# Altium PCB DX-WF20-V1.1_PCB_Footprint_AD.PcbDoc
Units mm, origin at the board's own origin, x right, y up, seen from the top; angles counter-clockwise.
Board outline 152.4 x 101.6 mm, 2 copper layers (Top, Bottom), stack 0.323 mm thick; 1 components, 0 nets, 52 pads, 0 vias.
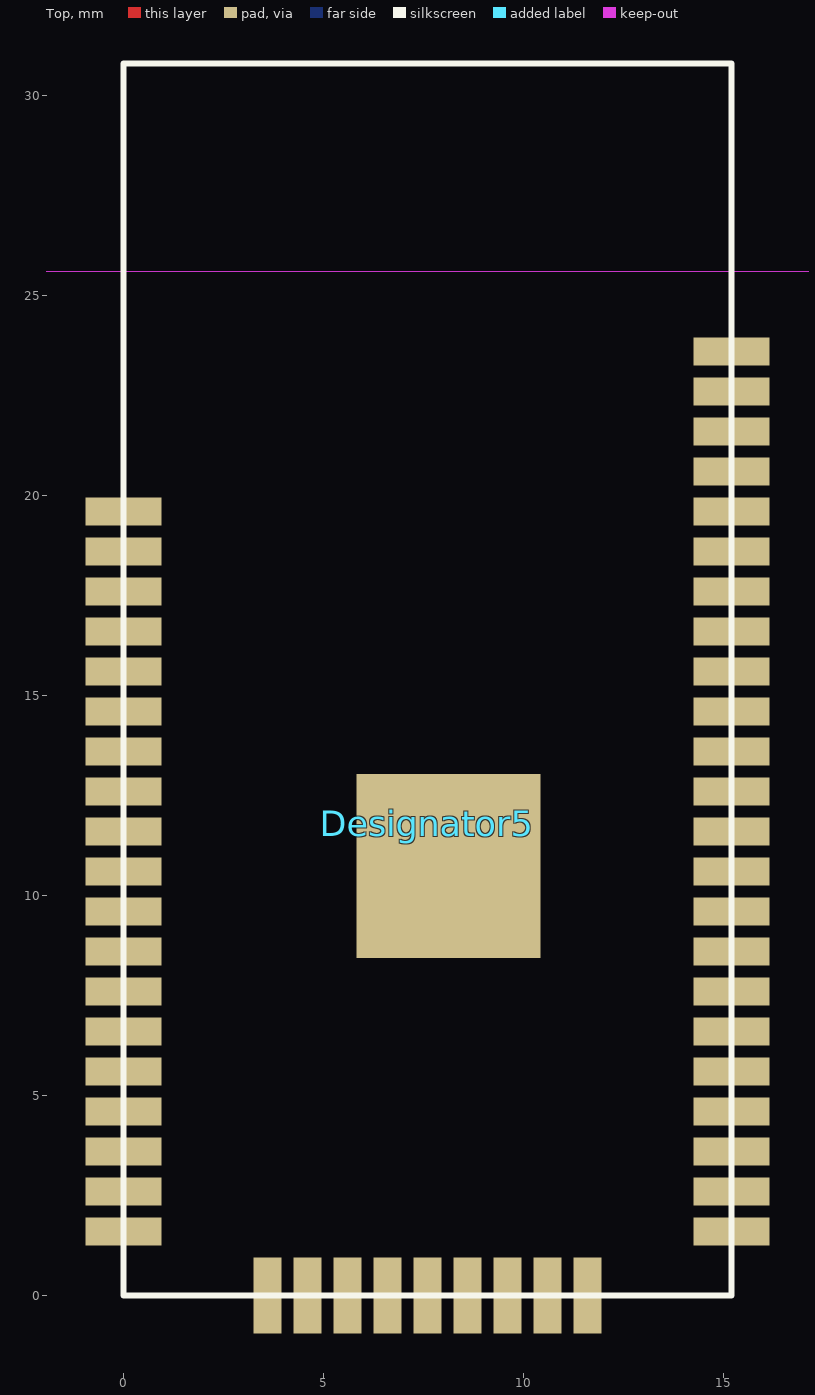
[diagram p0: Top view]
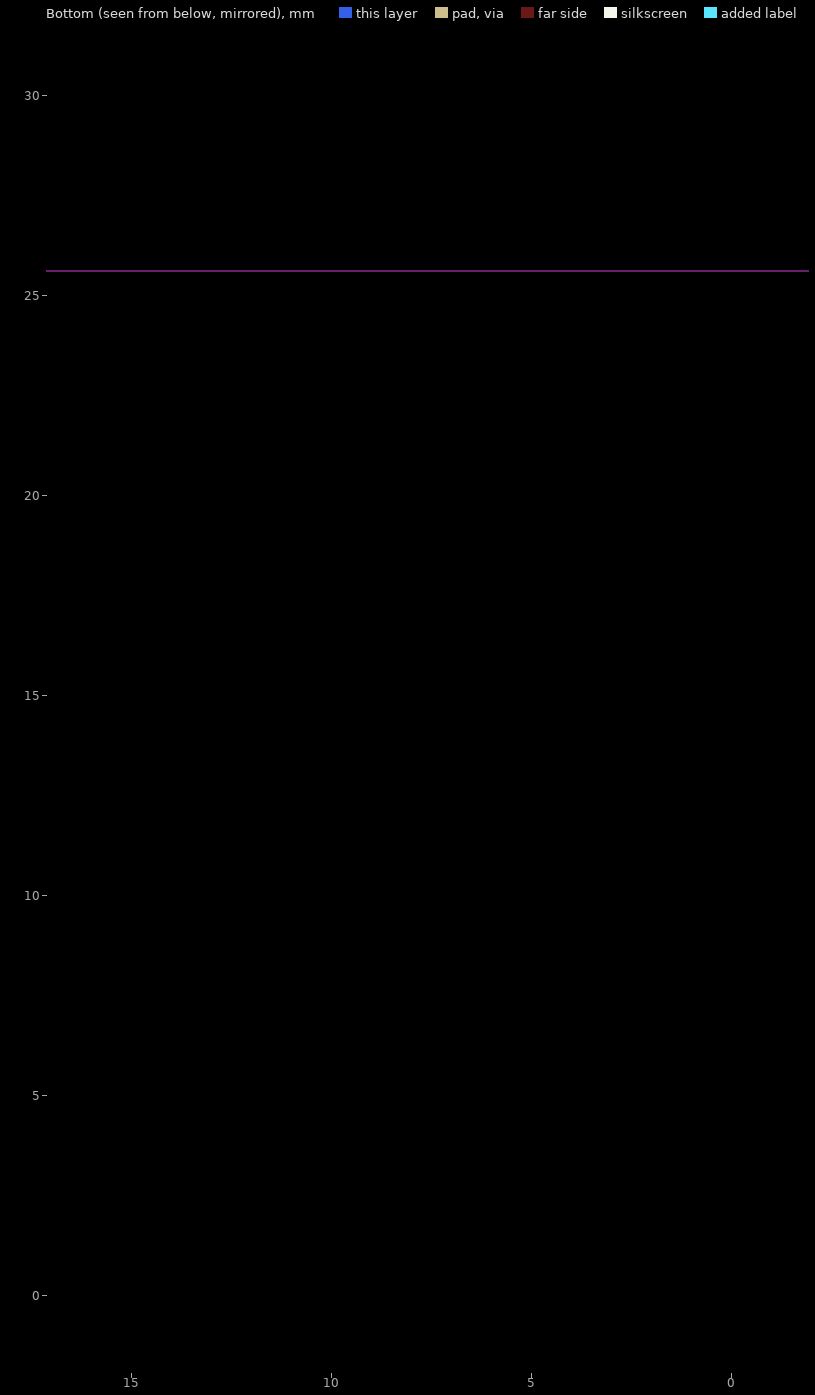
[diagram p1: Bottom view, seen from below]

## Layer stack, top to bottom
Solder Mask Top: solder mask 0.0102, Solder Resist, Dk 3.5
Top: signal copper 0.0343
Dielectric 1: dielectric 0.254, FR-4, Dk 4.3
Bottom: signal copper 0.0343
Solder Mask Bottom: solder mask 0.0102, Solder Resist, Dk 3.5

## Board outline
-694.363,-676.631 -541.963,-676.631 -541.963,-575.031 -694.363,-575.031

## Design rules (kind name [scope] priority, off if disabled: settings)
Clearance "'Default' PADS rule_17" [All] p1: gap=0.152 ignorepadtopadclearanceinfootprint=FALSE except(0: Arc-Hole Track-Hole SMDPad-Hole THPad-Hole Via-Hole Fill-Hole Poly-Hole Region-Hole Text-Hole)
Clearance "'Default' PADS rule_16" [InPolygon vs InPolygon] p2: gap=0.2 ignorepadtopadclearanceinfootprint=FALSE except(0: Arc-Hole Track-Hole SMDPad-Hole THPad-Hole Via-Hole Fill-Hole Poly-Hole Region-Hole Text-Hole)
Clearance "'Default' PADS rule_15" [All] p3: gap=0.152 ignorepadtopadclearanceinfootprint=FALSE except(0: Arc-Hole Track-Hole SMDPad-Hole THPad-Hole Via-Hole Fill-Hole Poly-Hole Region-Hole Text-Hole)
ComponentClearance "'Default' PADS rule_12" [All] p1: gap=0 collisioncheckmode=3 verticalgap=0.254 showdistances=FALSE
FlightTimeFalling "'Default' PADS rule_10" [All] p1: maximum=10.00
FlightTimeRising "'Default' PADS rule_9" [All] p1: maximum=10.00
Length "'Default' PADS rule_5" [All] p1: maxlimit=1270 minlimit=0
MatchedLengths "'Default' PADS rule_11" [InNetClass('All Nets')] p1: tolerance=5.08 checknetsindiffpair=TRUE checkdiffpairvsdiffpair=FALSE checkxsignals=FALSE checkothers=FALSE
MaxMinImpedance "'Default' PADS rule_8" [All] p1: minimum=50.00 maximum=150.0
ParallelSegment "'Default' PADS rule_7" [All] p1: limit=25.4 gap=5.08
ParallelSegment "'Default' PADS rule_6" [All] p2: limit=25.4 gap=5.08
PlaneClearance "'Default' PADS rule_14" [All] p1: clearance=0.2
PlaneConnect "Power Plane Connect Style - Via from round thru-hole global defaults" [IsVia] p1: planeconnectstyle=Direct reliefexpansion=0.508 reliefentries=4 reliefconductorwidth=0.381 reliefairgap=0.254
PlaneConnect "Power Plane Connect Style - Round thru-hole pad from global defaults" [IsPad And OnMultiLayer And (PadShape_MidLayer1 = 'Round') And (PadXSize_MidLayer1 = PadYSize_MidLayer1)] p2: planeconnectstyle=Direct reliefexpansion=0.508 reliefentries=4 reliefconductorwidth=0.381 reliefairgap=0.254
PlaneConnect "Power Plane Connect Style - Square thru-hole pad from global defaults" [IsPad And OnMultiLayer And ((PadShape_MidLayer1 = 'Rectangular') Or (PadShape_MidLayer1 = 'Octagonal') Or (PadShape_MidLayer1 = 'Rounded Rectangle')) And (PadXSize_MidLayer1 = PadYSize_MidLayer1)] p3: planeconnectstyle=Direct reliefexpansion=0.508 reliefentries=4 reliefconductorwidth=0.381 reliefairgap=0.254
PlaneConnect "Power Plane Connect Style - Rect thru-hole pad from global defaults" [IsPad And OnMultiLayer And ((PadShape_MidLayer1 = 'Rectangular') Or (PadShape_MidLayer1 = 'Octagonal') Or (PadShape_MidLayer1 = 'Rounded Rectangle')) And (PadXSize_MidLayer1 <> PadYSize_MidLayer1)] p4: planeconnectstyle=Direct reliefexpansion=0.508 reliefentries=4 reliefconductorwidth=0.381 reliefairgap=0.254
PlaneConnect "Power Plane Connect Style - Square-rect thru-hole pad from global defaults" [IsPad And OnMultiLayer And (PadShape_MidLayer1 = 'Rounded Rectangle') And (PadXSize_MidLayer1 = PadYSize_MidLayer1) And (Pad_CornerRadius_MidLayer1 = '0%')] p5: planeconnectstyle=Direct reliefexpansion=0.508 reliefentries=4 reliefconductorwidth=0.381 reliefairgap=0.254
PlaneConnect "Power Plane Connect Style - Oval thru-hole pad from global defaults" [IsPad And OnMultiLayer And (PadShape_MidLayer1 = 'Round') And (PadXSize_MidLayer1 <> PadYSize_MidLayer1)] p6: planeconnectstyle=Direct reliefexpansion=0.508 reliefentries=4 reliefconductorwidth=0.381 reliefairgap=0.254
PlaneConnect "Power Plane Connect Style - Round-oval thru-hole pad from global defaults" [IsPad And OnMultiLayer And (PadShape_MidLayer1 = 'Rounded Rectangle') And (PadXSize_MidLayer1 = PadYSize_MidLayer1) And (Pad_CornerRadius_MidLayer1 = '100%')] p7: planeconnectstyle=Direct reliefexpansion=0.508 reliefentries=4 reliefconductorwidth=0.381 reliefairgap=0.254
PolygonConnect "Polygon Connect Style - Bottom Round SMD from global defaults" [IsSMTPin And (PadShape_BottomLayer = 'Round') And (PadXSize_BottomLayer = PADYSize_BottomLayer) vs Layer = 'Bottom'] p1: connectstyle=Direct reliefconductorwidth=0.254 reliefentries=4 polygonreliefangle="45 Angle" airgapwidth=0.254
PolygonConnect "Polygon Connect Style - Top Round SMD from global defaults" [IsSMTPin And (PadShape_TopLayer = 'Round') And (PadXSize_TopLayer = PADYSize_TopLayer) vs Layer = 'Top'] p2: connectstyle=Direct reliefconductorwidth=0.254 reliefentries=4 polygonreliefangle="45 Angle" airgapwidth=0.254
PolygonConnect "Polygon Connect Style - Bottom Square SMD from global defaults 1" [IsSMTPin And (PadShape_BottomLayer = 'Rectangular') And (PadXSize_BottomLayer = PADYSize_BottomLayer) vs Layer = 'Bottom'] p3: connectstyle=Direct reliefconductorwidth=0.254 reliefentries=4 polygonreliefangle="45 Angle" airgapwidth=0.254
PolygonConnect "Polygon Connect Style - Bottom Square SMD from global defaults 2" [IsSMTPin And (PadShape_BottomLayer = 'Octagonal') And (PadXSize_BottomLayer = PADYSize_BottomLayer) vs Layer = 'Bottom'] p4: connectstyle=Direct reliefconductorwidth=0.254 reliefentries=4 polygonreliefangle="45 Angle" airgapwidth=0.254
PolygonConnect "Polygon Connect Style - Bottom Square SMD from global defaults 3" [IsSMTPin And (PadShape_BottomLayer = 'Rounded Rectangle') And (PadXSize_BottomLayer = PADYSize_BottomLayer) vs Layer = 'Bottom'] p5: connectstyle=Direct reliefconductorwidth=0.254 reliefentries=4 polygonreliefangle="45 Angle" airgapwidth=0.254
PolygonConnect "Polygon Connect Style - Top Square SMD from global defaults 1" [IsSMTPin And (PadShape_TopLayer = 'Rectangular') And (PadXSize_TopLayer = PADYSize_TopLayer) vs Layer = 'Top'] p6: connectstyle=Direct reliefconductorwidth=0.254 reliefentries=4 polygonreliefangle="45 Angle" airgapwidth=0.254
PolygonConnect "Polygon Connect Style - Top Square SMD from global defaults 2" [IsSMTPin And (PadShape_TopLayer = 'Octagonal') And (PadXSize_TopLayer = PADYSize_TopLayer) vs Layer = 'Top'] p7: connectstyle=Direct reliefconductorwidth=0.254 reliefentries=4 polygonreliefangle="45 Angle" airgapwidth=0.254
PolygonConnect "Polygon Connect Style - Top Square SMD from global defaults 3" [IsSMTPin And (PadShape_TopLayer = 'Rounded Rectangle') And (PadXSize_TopLayer = PADYSize_TopLayer) vs Layer = 'Top'] p8: connectstyle=Direct reliefconductorwidth=0.254 reliefentries=4 polygonreliefangle="45 Angle" airgapwidth=0.254
PolygonConnect "Polygon Connect Style - Bottom Rect SMD from global defaults 1" [IsSMTPin And (PadShape_BottomLayer = 'Rectangular') And (PadXSize_BottomLayer <> PADYSize_BottomLayer) vs Layer = 'Bottom'] p9: connectstyle=Direct reliefconductorwidth=0.254 reliefentries=4 polygonreliefangle="45 Angle" airgapwidth=0.254
PolygonConnect "Polygon Connect Style - Bottom Rect SMD from global defaults 2" [IsSMTPin And (PadShape_BottomLayer = 'Octagonal') And (PadXSize_BottomLayer <> PADYSize_BottomLayer) vs Layer = 'Bottom'] p10: connectstyle=Direct reliefconductorwidth=0.254 reliefentries=4 polygonreliefangle="45 Angle" airgapwidth=0.254
PolygonConnect "Polygon Connect Style - Bottom Rect SMD from global defaults 3" [IsSMTPin And (PadShape_BottomLayer = 'Rounded Rectangle') And (PadXSize_BottomLayer <> PADYSize_BottomLayer) vs Layer = 'Bottom'] p11: connectstyle=Direct reliefconductorwidth=0.254 reliefentries=4 polygonreliefangle="45 Angle" airgapwidth=0.254
PolygonConnect "Polygon Connect Style - Bottom Square-rect SMD pad from global defaults" [IsSMTPin And (PadShape_BottomLayer = 'Rounded Rectangle') And (PadXSize_BottomLayer = PADYSize_BottomLayer) And (Pad_CornerRadius_BottomLayer = '0%') vs Layer = 'Bottom'] p12: connectstyle=Direct reliefconductorwidth=0.254 reliefentries=4 polygonreliefangle="45 Angle" airgapwidth=0.254
PolygonConnect "Polygon Connect Style - Top Rect SMD from global defaults 1" [IsSMTPin And (PadShape_TopLayer = 'Rectangular') And (PadXSize_TopLayer <> PADYSize_TopLayer) vs Layer = 'Top'] p13: connectstyle=Direct reliefconductorwidth=0.254 reliefentries=4 polygonreliefangle="45 Angle" airgapwidth=0.254
PolygonConnect "Polygon Connect Style - Top Rect SMD from global defaults 2" [IsSMTPin And (PadShape_TopLayer = 'Octagonal') And (PadXSize_TopLayer <> PADYSize_TopLayer) vs Layer = 'Top'] p14: connectstyle=Direct reliefconductorwidth=0.254 reliefentries=4 polygonreliefangle="45 Angle" airgapwidth=0.254
PolygonConnect "Polygon Connect Style - Top Rect SMD from global defaults 3" [IsSMTPin And (PadShape_TopLayer = 'Rounded Rectangle') And (PadXSize_TopLayer <> PADYSize_TopLayer) vs Layer = 'Top'] p15: connectstyle=Direct reliefconductorwidth=0.254 reliefentries=4 polygonreliefangle="45 Angle" airgapwidth=0.254
PolygonConnect "Polygon Connect Style - Top Square-rect SMD pad from global defaults" [IsSMTPin And (PadShape_TopLayer = 'Rounded Rectangle') And (PadXSize_TopLayer = PADYSize_TopLayer) And (Pad_CornerRadius_TopLayer = '0%') vs Layer = 'Top'] p16: connectstyle=Direct reliefconductorwidth=0.254 reliefentries=4 polygonreliefangle="45 Angle" airgapwidth=0.254
PolygonConnect "Polygon Connect Style - Bottom Oval SMD from global defaults" [IsSMTPin And (PadShape_BottomLayer = 'Round') And (PadXSize_BottomLayer <> PADYSize_BottomLayer) vs Layer = 'Bottom'] p17: connectstyle=Direct reliefconductorwidth=0.254 reliefentries=4 polygonreliefangle="45 Angle" airgapwidth=0.254
PolygonConnect "Polygon Connect Style - Bottom Round-oval SMD pad from global defaults" [IsSMTPin And (PadShape_BottomLayer = 'Rounded Rectangle') And (PadXSize_BottomLayer = PADYSize_BottomLayer) And (Pad_CornerRadius_BottomLayer = '100%') vs Layer = 'Bottom'] p18: connectstyle=Direct reliefconductorwidth=0.254 reliefentries=4 polygonreliefangle="45 Angle" airgapwidth=0.254
PolygonConnect "Polygon Connect Style - Top Oval SMD from global defaults" [IsSMTPin And (PadShape_TopLayer = 'Round') And (PadXSize_TopLayer <> PADYSize_TopLayer) vs Layer = 'Top'] p19: connectstyle=Direct reliefconductorwidth=0.254 reliefentries=4 polygonreliefangle="45 Angle" airgapwidth=0.254
PolygonConnect "Polygon Connect Style - Top Round-oval SMD pad from global defaults" [IsSMTPin And (PadShape_TopLayer = 'Rounded Rectangle') And (PadXSize_TopLayer = PADYSize_TopLayer) And (Pad_CornerRadius_TopLayer = '100%') vs Layer = 'Top'] p20: connectstyle=Direct reliefconductorwidth=0.254 reliefentries=4 polygonreliefangle="45 Angle" airgapwidth=0.254
PolygonConnect "Polygon Connect Style - Via from round thru-hole global defaults_18" [IsVia] p21: connectstyle=Direct reliefconductorwidth=0.381 reliefentries=4 polygonreliefangle="45 Angle" airgapwidth=0.254
PolygonConnect "Polygon Connect Style - Bottom Round thru-hole pad from global defaults" [IsPad And OnMultiLayer And (PadShape_BottomLayer = 'Round') And (PadXSize_BottomLayer = PADYSize_BottomLayer) vs Layer = 'Bottom'] p22: connectstyle=Direct reliefconductorwidth=0.381 reliefentries=4 polygonreliefangle="45 Angle" airgapwidth=0.254
PolygonConnect "Polygon Connect Style - Via from round thru-hole global defaults" [IsVia] p23: connectstyle=Direct reliefconductorwidth=0.381 reliefentries=4 polygonreliefangle="45 Angle" airgapwidth=0.254
PolygonConnect "Polygon Connect Style - Top Round thru-hole pad from global defaults" [IsPad And OnMultiLayer And (PadShape_TopLayer = 'Round') And (PadXSize_TopLayer = PADYSize_TopLayer) vs Layer = 'Top'] p24: connectstyle=Direct reliefconductorwidth=0.381 reliefentries=4 polygonreliefangle="45 Angle" airgapwidth=0.254
PolygonConnect "Polygon Connect Style - Bottom Square thru-hole pad from global defaults" [IsPad And OnMultiLayer And ((PadShape_BottomLayer = 'Rectangular') Or (PadShape_BottomLayer = 'Octagonal') Or (PadShape_BottomLayer = 'Rounded Rectangle')) And (PadXSize_BottomLayer = PADYSize_BottomLayer) vs Layer = 'Bottom'] p25: connectstyle=Direct reliefconductorwidth=0.381 reliefentries=4 polygonreliefangle="45 Angle" airgapwidth=0.254
PolygonConnect "Polygon Connect Style - Top Square thru-hole pad from global defaults" [IsPad And OnMultiLayer And ((PadShape_TopLayer = 'Rectangular') Or (PadShape_TopLayer = 'Octagonal') Or (PadShape_TopLayer = 'Rounded Rectangle')) And (PadXSize_TopLayer = PADYSize_TopLayer) vs Layer = 'Top'] p26: connectstyle=Direct reliefconductorwidth=0.381 reliefentries=4 polygonreliefangle="45 Angle" airgapwidth=0.254
PolygonConnect "Polygon Connect Style - Bottom Rect thru-hole pad from global defaults" [IsPad And OnMultiLayer And ((PadShape_BottomLayer = 'Rectangular') Or (PadShape_BottomLayer = 'Octagonal') Or (PadShape_BottomLayer = 'Rounded Rectangle')) And (PadXSize_BottomLayer <> PADYSize_BottomLayer) vs Layer = 'Bottom'] p27: connectstyle=Direct reliefconductorwidth=0.381 reliefentries=4 polygonreliefangle="45 Angle" airgapwidth=0.254
PolygonConnect "Polygon Connect Style - Bottom Square-rect thru-hole pad from global defaults" [IsPad And OnMultiLayer And (PadShape_BottomLayer = 'Rounded Rectangle') And (PadXSize_BottomLayer = PADYSize_BottomLayer) And (Pad_CornerRadius_BottomLayer = '0%') vs Layer = 'Bottom'] p28: connectstyle=Direct reliefconductorwidth=0.381 reliefentries=4 polygonreliefangle="45 Angle" airgapwidth=0.254
PolygonConnect "Polygon Connect Style - Top Rect thru-hole pad from global defaults" [IsPad And OnMultiLayer And ((PadShape_TopLayer = 'Rectangular') Or (PadShape_TopLayer = 'Octagonal') Or (PadShape_TopLayer = 'Rounded Rectangle')) And (PadXSize_TopLayer <> PADYSize_TopLayer) vs Layer = 'Top'] p29: connectstyle=Direct reliefconductorwidth=0.381 reliefentries=4 polygonreliefangle="45 Angle" airgapwidth=0.254
PolygonConnect "Polygon Connect Style - Top Square-rect thru-hole pad from global defaults" [IsPad And OnMultiLayer And (PadShape_TopLayer = 'Rounded Rectangle') And (PadXSize_TopLayer = PADYSize_TopLayer) And (Pad_CornerRadius_TopLayer = '0%') vs Layer = 'Top'] p30: connectstyle=Direct reliefconductorwidth=0.381 reliefentries=4 polygonreliefangle="45 Angle" airgapwidth=0.254
PolygonConnect "Polygon Connect Style - Bottom Oval thru-hole pad from global defaults" [IsPad And OnMultiLayer And (PadShape_BottomLayer = 'Round') And (PadXSize_BottomLayer <> PADYSize_BottomLayer) vs Layer = 'Bottom'] p31: connectstyle=Direct reliefconductorwidth=0.381 reliefentries=4 polygonreliefangle="45 Angle" airgapwidth=0.254
PolygonConnect "Polygon Connect Style - Bottom Round-oval thru-hole pad from global defaults" [IsPad And OnMultiLayer And (PadShape_BottomLayer = 'Rounded Rectangle') And (PadXSize_BottomLayer = PADYSize_BottomLayer) And (Pad_CornerRadius_BottomLayer = '100%') vs Layer = 'Bottom'] p32: connectstyle=Direct reliefconductorwidth=0.381 reliefentries=4 polygonreliefangle="45 Angle" airgapwidth=0.254
PolygonConnect "Polygon Connect Style - Top Oval thru-hole pad from global defaults" [IsPad And OnMultiLayer And (PadShape_TopLayer = 'Round') And (PadXSize_TopLayer <> PADYSize_TopLayer) vs Layer = 'Top'] p33: connectstyle=Direct reliefconductorwidth=0.381 reliefentries=4 polygonreliefangle="45 Angle" airgapwidth=0.254
PolygonConnect "Polygon Connect Style - Top Round-oval thru-hole pad from global defaults" [IsPad And OnMultiLayer And (PadShape_TopLayer = 'Rounded Rectangle') And (PadXSize_TopLayer = PADYSize_TopLayer) And (Pad_CornerRadius_TopLayer = '100%') vs Layer = 'Top'] p34: connectstyle=Direct reliefconductorwidth=0.381 reliefentries=4 polygonreliefangle="45 Angle" airgapwidth=0.254
PolygonConnect [All] p35: connectstyle=Relief reliefconductorwidth=0.254 reliefentries=4 polygonreliefangle="90 Angle" airgapwidth=0.254
RoutingLayers "'Default' PADS rule_3" [All] p1: top layer_v5=TRUE bottom layer_v5=TRUE
RoutingPriority "'Default' PADS rule_2" [All] p1: routingpriority=3
RoutingTopology "'Default' PADS rule" [All] p1: topology=Shortest
RoutingVias "'Default' PADS rule_4" [All] p1: holewidth=0.23 width=0.5 viastyle="Through Hole" minholewidth=0.23 minwidth=0.5 maxholewidth=0.23 maxwidth=0.5
SolderMaskExpansion [All] p1: expansion=0.102 istentingtop=FALSE
Width "'Default' PADS rule_13" [All] p1: maxlimit=0.152 minlimit=0.152 preferedwidth=0.152
24 further rules are at their usual default settings.

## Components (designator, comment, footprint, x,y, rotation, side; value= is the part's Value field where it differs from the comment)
Designator5 "Comment" PCBComponent_1 0,30.8 r270 top

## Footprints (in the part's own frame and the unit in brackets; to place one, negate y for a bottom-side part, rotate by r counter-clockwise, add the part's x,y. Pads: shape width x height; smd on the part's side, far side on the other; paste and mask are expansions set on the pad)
PCBComponent_1 [mm]
  rect 0.7x1.9 / inner rrect0% 0.7x0.7 / far side rect 0x0 all layers, no hole: 1(11.2,0)
  rect 0.7x1.9 / inner rrect0% 0x0 / far side rect 0x0 all layers, no hole: 2(12.2,0) 3(13.2,0) 4(14.2,0) 5(15.2,0) 6(16.2,0) 7(17.2,0) 8(18.2,0) 9(19.2,0) 10(20.2,0) 11(21.2,0) 12(22.2,0) 13(23.2,0) 14(24.2,0) 15(25.2,0) 16(26.2,0) 17(27.2,0) 18(28.2,0) 19(29.2,0) 29(29.2,15.2) 30(28.2,15.2) 31(27.2,15.2) 32(26.2,15.2) 33(25.2,15.2) 34(24.2,15.2) 35(23.2,15.2) 36(22.2,15.2) 37(21.2,15.2) 38(20.2,15.2) 39(19.2,15.2) 40(18.2,15.2) 41(17.2,15.2) 42(16.2,15.2) 43(15.2,15.2) 44(14.2,15.2) 45(13.2,15.2) 46(12.2,15.2) 47(11.2,15.2) 48(10.2,15.2) 49(9.2,15.2) 50(8.2,15.2) 51(7.2,15.2)
  rect 1.9x0.7 / inner rrect0% 0x0 / far side rect 0x0 all layers, no hole: 20(30.8,3.6) 22(30.8,5.6) 23(30.8,6.6) 24(30.8,7.6) 25(30.8,8.6) 26(30.8,9.6) 28(30.8,11.6)
  rrect0% 1.9x0.7 / inner rrect0% 0x0 / far side rect 0x0 all layers, no hole: 21(30.8,4.6) 27(30.8,10.6)
  rect 4.6x4.6 smd: GND(20.066,8.128)
  silkscreen extent 0,0 30.8,15.2

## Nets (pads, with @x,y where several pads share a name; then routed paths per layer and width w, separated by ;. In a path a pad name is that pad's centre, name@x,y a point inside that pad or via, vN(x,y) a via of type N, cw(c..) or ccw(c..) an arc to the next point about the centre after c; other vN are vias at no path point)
pads on no net: Designator5.1 Designator5.2 Designator5.3 Designator5.4 Designator5.5 Designator5.6 Designator5.7 Designator5.8 Designator5.9 Designator5.10 Designator5.11 Designator5.12 Designator5.13 Designator5.14 Designator5.15 Designator5.16 Designator5.17 Designator5.18 Designator5.19 Designator5.20 Designator5.21 Designator5.22 Designator5.23 Designator5.24 Designator5.25 Designator5.26 Designator5.27 Designator5.28 Designator5.29 Designator5.30 Designator5.31 Designator5.32 Designator5.33 Designator5.34 Designator5.35 Designator5.36 Designator5.37 Designator5.38 Designator5.39 Designator5.40 Designator5.41 Designator5.42 Designator5.43 Designator5.44 Designator5.45 Designator5.46 Designator5.47 Designator5.48 Designator5.49 Designator5.50 Designator5.51 Designator5.GND

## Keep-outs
Keep-Out Layer:
  region: -5,35.8 -5,25.6 20.2,25.6 20.2,35.8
